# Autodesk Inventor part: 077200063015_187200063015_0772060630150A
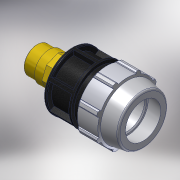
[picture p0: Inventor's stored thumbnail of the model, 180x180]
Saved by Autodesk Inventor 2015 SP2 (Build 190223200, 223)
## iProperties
Created: 2017-02
Part Number: 077200063015_187200063015_0772060630150A
Material: PVC-Piping
Description: PLASSON MALE ADAPTOR INTEGRAL BRASS THREAD 63-1.1/2"
Document SubType Name: Modeling
Designer: KIM
Mass: 92.6774 g
Surface Area: 199.44 cm^2
Volume: 66.1981 cm^3
Density: 1.4 g/cm^3
Appearance: PTFE
Author: KIM
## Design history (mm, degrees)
derived "07720.ipt"
feature "Solid1::07720.ipt"
tag "TaggingFeature1"
body "Solid1"
other parameters: "d2" = 63, "d4" = 27.14286, "d5" = 27.14286, "d7" = 113, "d8" = 84.75, "d9" = 27.14286, "d11" = 5.42857, "d12" = 90.4, "d13" = 120 deg, "d14" = 88.2, "d15" = 10 deg, "d16" = 101.7, "d18" = 3.15, "d19" = 35 deg, "d20" = 17.5 deg, "d21" = 105.09, "d23" = 0, "d25" = 360 deg, "d27" = 2.26, "d34" = 5.65, "d36" = 0, "d42" = 38, "d43" = 3.39, "d46" = 1.89, "d49" = 123, "d53" = 1.26, "d55" = 360 deg, "d59" = 38, "d60" = 47.803, "d61" = 52.5833, "d62" = 22, "d63" = 63.33333, "d64" = 33.4621, "d66" = 23.14406, "d67" = 0, "d68" = 1.26, "d71" = 30 deg, "d72" = 43.0227, "d_" = 63, "E_" = 113, "l_" = 123, "l_2" = 22, "R_" = 47.803, "d73" = 38.57343
